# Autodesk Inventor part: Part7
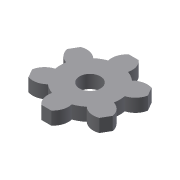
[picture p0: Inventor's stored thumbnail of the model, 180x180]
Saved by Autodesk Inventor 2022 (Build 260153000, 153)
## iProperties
Created: 2002-01
Part Number: Part7
Document SubType Name: Modeling
Designer: ***
Density: 1 g/cm^3
Material: Generic
Appearance: Default
Control State: 0
Master: False
Checked Out: False
Shininess: 77.0
Angle Display Precision: 2
Document Length Units: 11269
Document Angle Units: 11279
Document Time Units: 11290
Document Mass Units: 11283
Document Length Units Precision: 3
Document Angle Units Precision: 2
Density: 0.0
Volumn: 0.0
Area: 0.0
PropertySet Name: Model Information
Author: ***
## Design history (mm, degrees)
sketch "Sketch1"
  geometry: L1 (-3.771, 33.333)-(3.771, 33.333); L2 (-30.753, 13.401)-(-26.982, 19.933); L3 (-30.753, -13.401)-(-26.982, -19.933); L4 (-3.771, -33.333)-(3.771, -33.333); L5 (30.753, 13.401)-(26.982, 19.933); L6 (30.753, -13.401)-(26.982, -19.933); C1 r 8 at (0, 0); A1 r 11.863 centre (3.952, 24.328) between (-3.771, 33.333) and (-7.559, 21.457); A2 r 11.863 centre (-3.952, 24.328) between (7.559, 21.457) and (3.771, 33.333); A3 r 11.863 centre (-19.093, 15.587) between (-30.753, 13.401) and (-22.362, 4.182); A4 r 11.863 centre (-23.045, 8.742) between (-14.803, 17.275) and (-26.982, 19.933); A5 r 22.749 centre (0, 0) between (-7.559, 21.457) and (-14.803, 17.275); A6 r 11.863 centre (-23.045, -8.742) between (-26.982, -19.933) and (-14.803, -17.275); A7 r 11.863 centre (-19.093, -15.587) between (-22.362, -4.182) and (-30.753, -13.401); A8 r 11.863 centre (3.952, -24.328) between (-7.559, -21.457) and (-3.771, -33.333); A9 r 11.863 centre (-3.952, -24.328) between (3.771, -33.333) and (7.559, -21.457); A10 r 11.863 centre (23.045, 8.742) between (26.982, 19.933) and (14.803, 17.275); A11 r 11.863 centre (19.093, 15.587) between (22.362, 4.182) and (30.753, 13.401); A12 r 11.863 centre (19.093, -15.587) between (30.753, -13.401) and (22.362, -4.182); A13 r 11.863 centre (23.045, -8.742) between (14.803, -17.275) and (26.982, -19.933); A14 r 22.749 centre (0, 0) between (-22.362, 4.182) and (-22.362, -4.182); A15 r 22.749 centre (0, 0) between (-14.803, -17.275) and (-7.559, -21.457); A16 r 22.749 centre (0, 0) between (7.559, -21.457) and (14.803, -17.275); A17 r 22.749 centre (0, 0) between (22.362, -4.182) and (22.362, 4.182); A18 r 22.749 centre (0, 0) between (14.803, 17.275) and (7.559, 21.457)
  constraints: 36 point on circle, 19 centre point, 12 end point, 1 coincident
  dimensions: "d2" = 16 diameter of C1
extrude "Extrusion1" new body sketch "Sketch1" distance "d0" = 10; taper "d1" = 0 deg
body "Solid1"
